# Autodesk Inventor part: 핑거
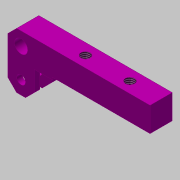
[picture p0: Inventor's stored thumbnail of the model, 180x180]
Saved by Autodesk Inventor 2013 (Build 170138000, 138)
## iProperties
Created: 2020-02
Part Number: 핑거
Material: 알루미늄 6061
Document SubType Name: Modeling
Designer: mduedu
Density: 1 g/cm^3
Author: mduedu
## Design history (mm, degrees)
sketch "스케치1"
  geometry: L1 (0, 0)-(12, 0); L2 (64, 14)-(64, 25); L3 (64, 25)-(0, 25); L4 (0, 25)-(0, 0); L5 (12, 0)-(12, 13); L6 (12, 13)-(20, 13); L7 (64, 14)-(20, 14); L8 (20, 14)-(20, 13)
  constraints: 16 end point, 2 horizontal, 2 parallel, 1 perpendicular, 1 vertical
  dimensions: "d0" = 64 distance of L2.end L3.end; "d2" = 12 distance of L1.start L1.end; "d3" = 25 distance of L3.end L1.start; "d4" = 11 distance of L2.start L2.end; "d5" = 12 distance between parallel lines of L6 L3; "d6" = 44 distance of L2.start L7.end
extrude "돌출1" new body sketch "스케치1" stored distance "d7" = 10; taper "d8" = 0 deg
chamfer "모따기1" distance "d9" = 4; stored, may be unused: second distance "d10" = 2, angle "d11" = 45 deg
sketch "스케치2"
  geometry: L1 (2.5, -4)-(7.5, -4); L2 (7.5, -4)-(7.5, 9); L3 (7.5, 9)-(2.5, 9); L4 (2.5, 9)-(2.5, -4); L5 (10, 21)-(0, 21) reference; 2 further points
  constraints: 8 end point, 2 parallel, 1 coincident, 1 horizontal, 1 midpoint, 1 perpendicular
  dimensions: "d12" = 5 distance of L1.start L1.end; "d15" = 12 distance between parallel lines of L3 L5
extrude "돌출2" cut sketch "스케치2" stored distance "d16" = 10; taper "d17" = 0 deg
sketch "스케치3"
  geometry: L1 (0, 4)-(0, 21) reference; L2 (4, 25)-(64, 25) reference; C1 r 2 at (6, 6); C2 r 3 at (6, 19); 1 further point
  constraints: 2 centre point, 1 vertical alignment
  dimensions: "d18" = 6 distance from line of C2.centre L1; "d19" = 6 distance from line of C2.centre L2; "d20" = 13 distance of C1.centre C2.centre; "d21" = 6 diameter of C2; "d22" = 4 diameter of C1
extrude "돌출3" cut sketch "스케치3" stored distance "d23" = 10; taper "d24" = 0 deg
sketch "스케치4"
  geometry: L1 (0, 10)-(0, 0) reference; 3 further points
  constraints: 2 horizontal alignment
  dimensions: "d25" = 14 distance from line of point (-14, 5) L1; "d26" = 20 distance of point (-34, 5) point (-14, 5)
hole "구멍1" sketch "스케치4" at (-34, 5), (-14, 5) diameter "d27" = 4.134; stored, may be unused: countersink angle "d31" = 90 deg, drill point angle "d33" = 118 deg; dims "d28" = 6, "d29" = 4, "d30" = 2, "d32" = 8
node "솔리드1"
